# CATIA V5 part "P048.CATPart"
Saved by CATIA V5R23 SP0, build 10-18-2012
Part number: 05-LICP-T02-E-S02-P048
Definition: Coulisseau
Bounding box of the stored display mesh (mm): x -15 to 15, y -15 to 15, z 0 to 144
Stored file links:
  C:\wamp\www\COURS\CONCEPTION GMP1\TITRE 02-SEMESTRE 2\03-TP7-PRESSE MECANIQUE\eleve\P048.CATPart
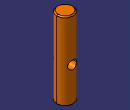
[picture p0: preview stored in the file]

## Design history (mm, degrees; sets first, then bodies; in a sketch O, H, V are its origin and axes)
Body1 (main body)
  Sketch1 on xy-plane, origin (0, 0, 0), H (1, 0, 0), V (0, 1, 0)
    circle A1 centre (0, 0) radius 15
    radius A1 = 15
  Pad1: profile Sketch1, direction (0, 0, 1), length 144
  Chamfer1: length 2, angle 45, on edge [face of Pad1 | face of Pad1] (x2)
  Sketch2 on face of Pad1, origin (0, 0, 0), H (1, 0, 0), V (0, -1, 0)
    point P1 (0, 0)
    reference projected circle E1 centre (0, 0) radius 13 from edge [face of Pad1 | face of Chamfer1]
    concentricity: P1 E1
  Hole1: placed by Sketch2, at (0, 0, 0) direction (0, 0, 1), diameter 17.294, depth 42, V-bottom angle 120, threaded "M20", thread diameter 20, thread depth 38, pitch 2.5
  Sketch3 on zx-plane, origin (0, 0, 0), H (-1, 0, 0), V (0, 0, 1)
    circle A1 centre (0, 64) radius 8
    point P1 (0, 64)
    radius A1 = 8
    distance P1 H = 64
    coincidence: P1 V
  Pocket1: profile Sketch3, direction (0, -1, 0), length 20, mirrored extent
